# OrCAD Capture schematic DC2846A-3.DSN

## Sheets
1 PAGE2: size A
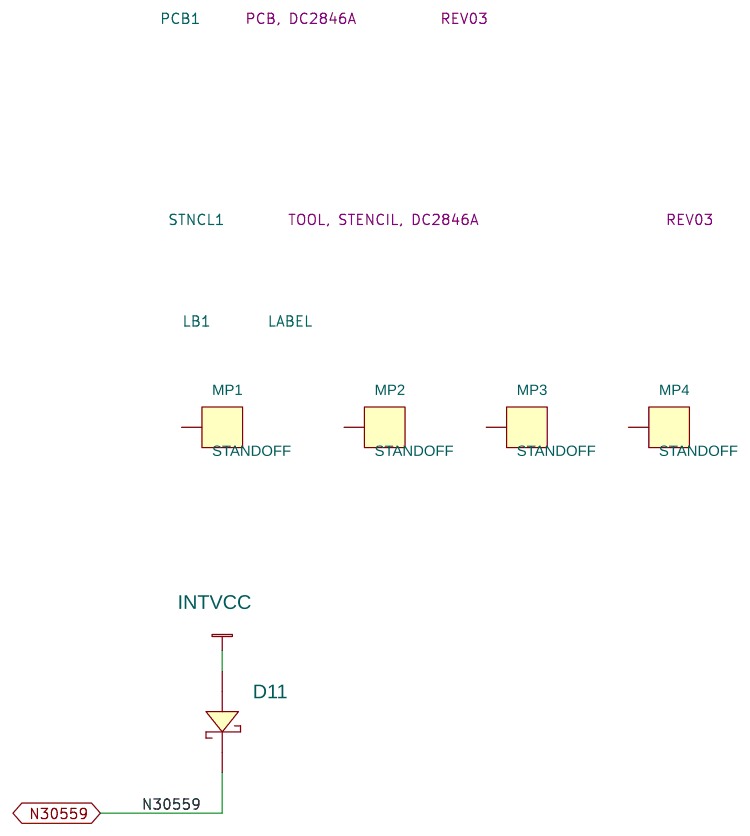
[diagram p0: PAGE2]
2 PAGE1: size Custom; title: HIGH EFFICIENCY, HIGH STEP-DOWN RATIO, SWITCHED CAPACITOR INVERTER; company: LINEAR TECHNOLOGY CORP.; note: DEMO BOARD BILL OF MATERIALS; note: HIGH EFFICIENCY SYNCHRONOUS STEP-UP SUPPLY
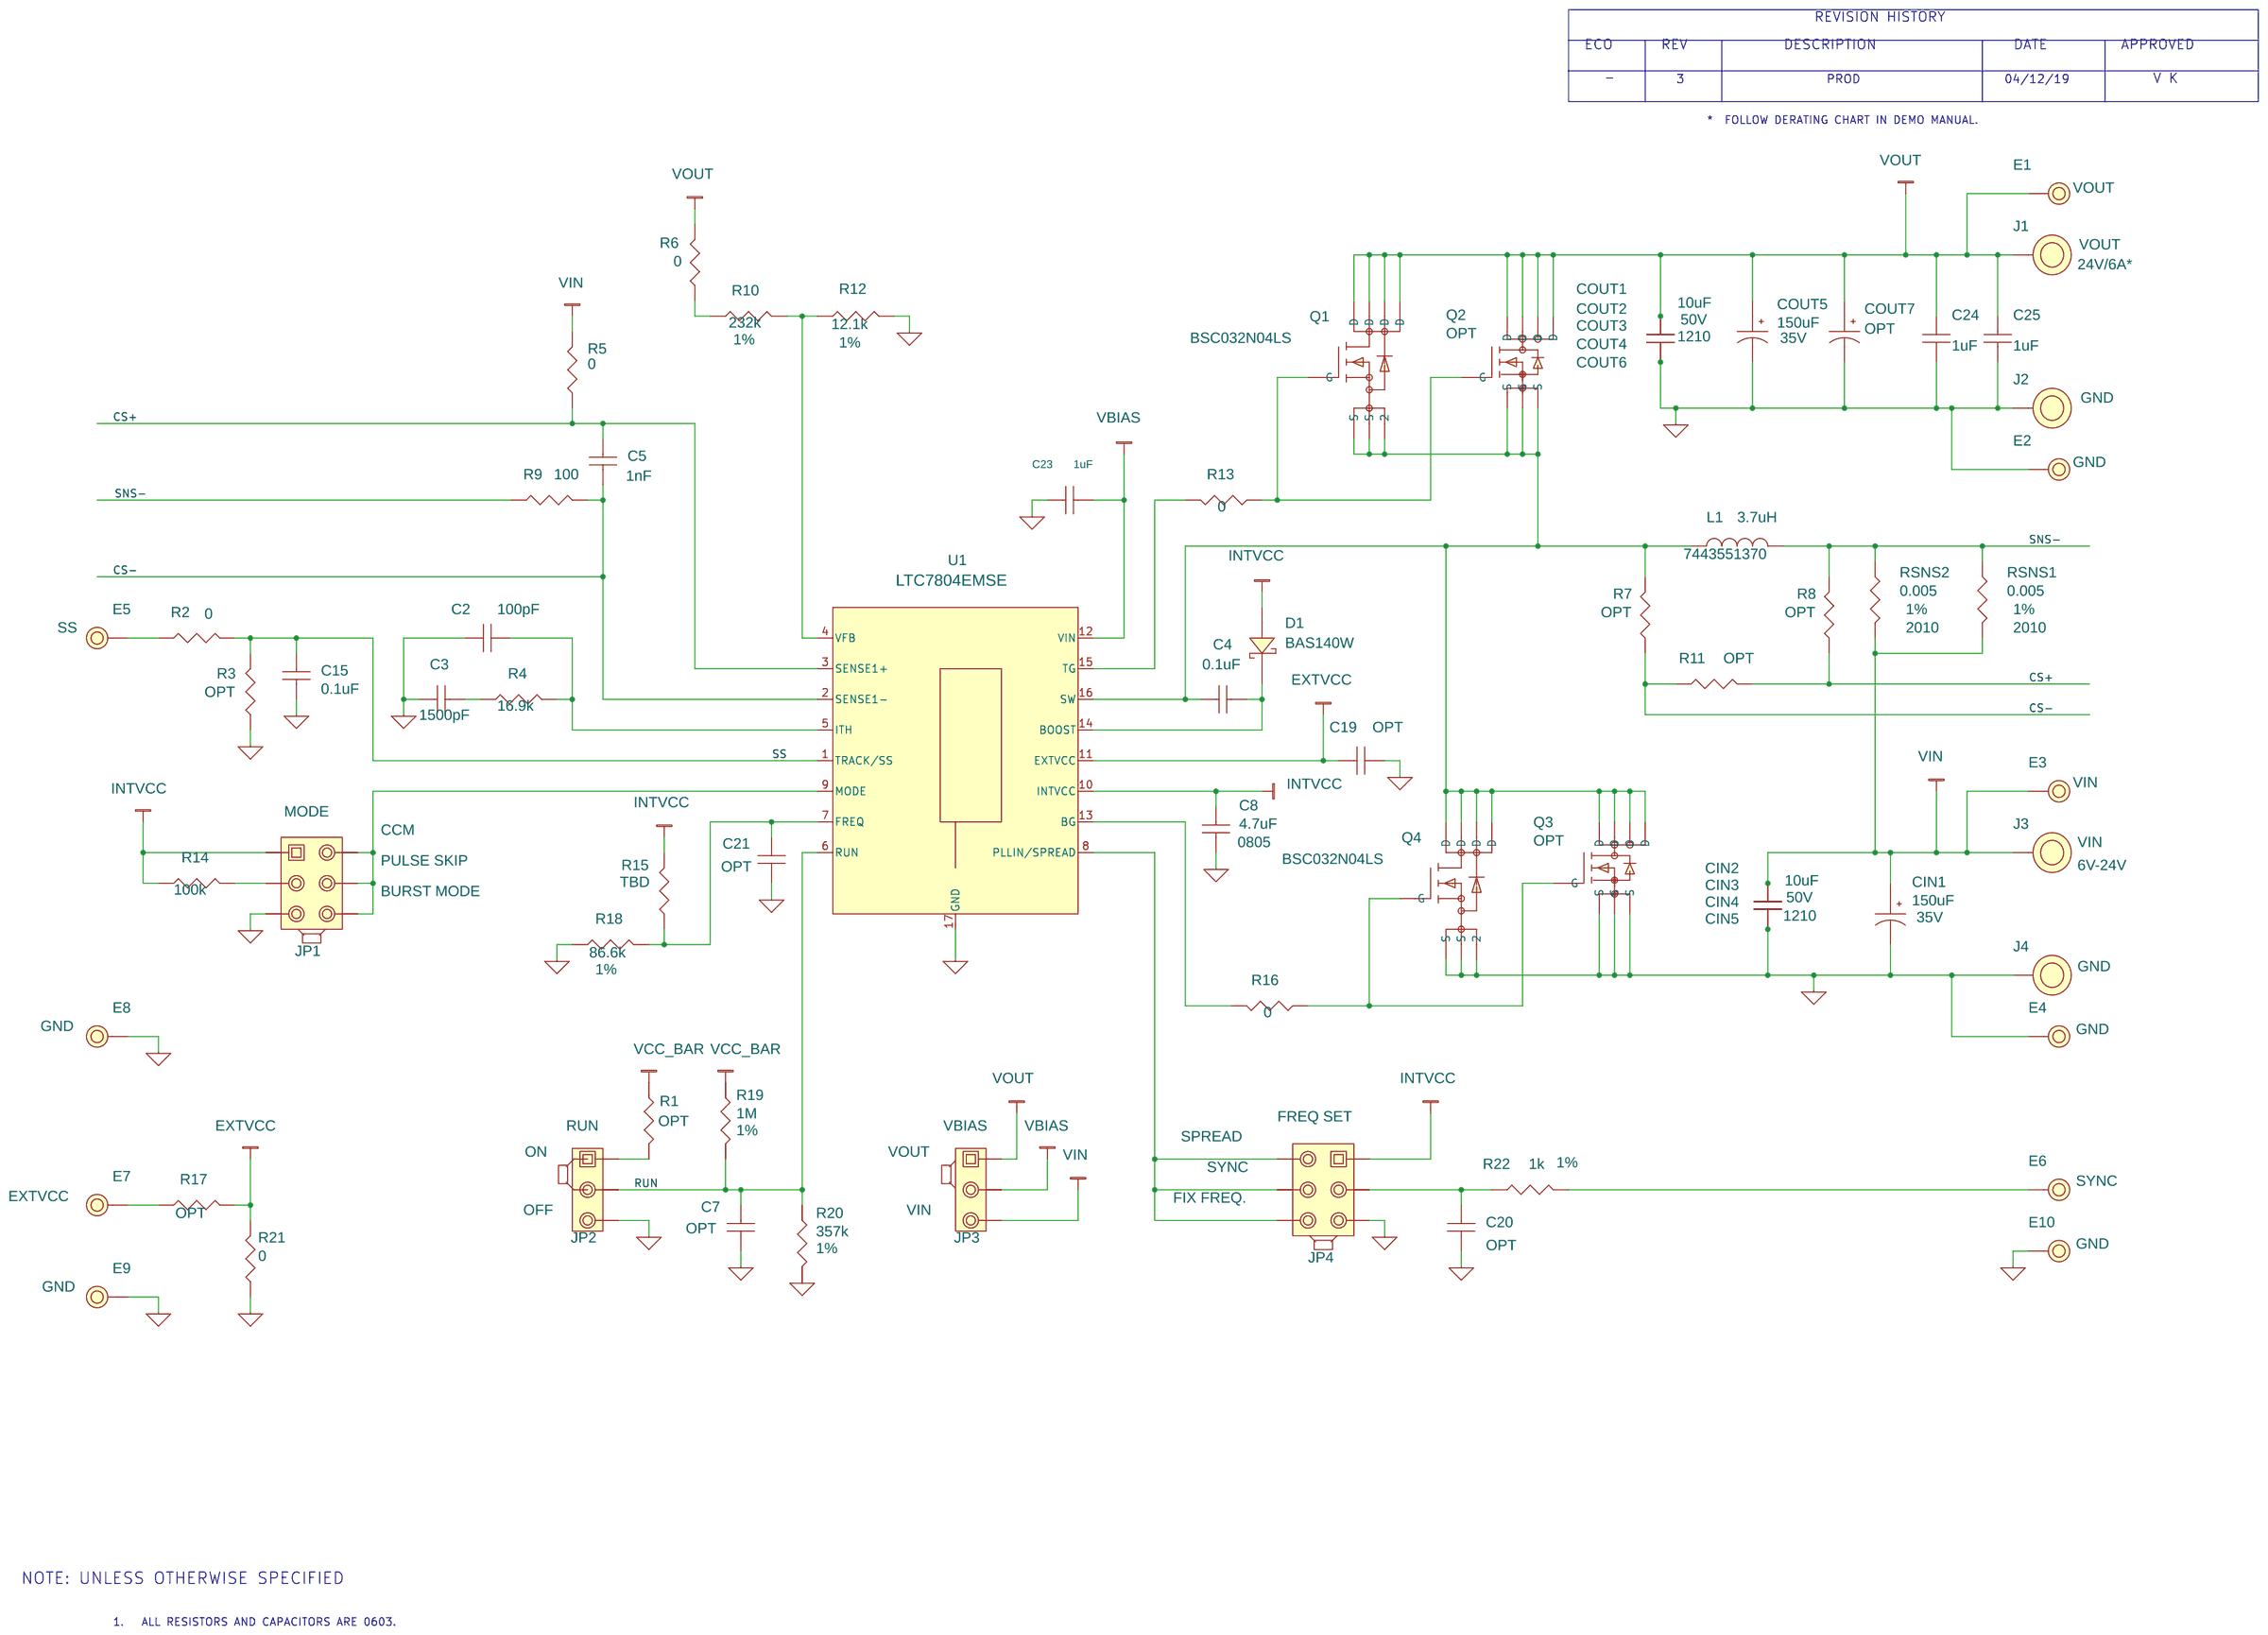
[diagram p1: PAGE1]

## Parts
sheet PAGE1
C2  100pF  [CC0603N]
C3  1500pF  [CC0603N]
C4  0.1uF  [CC0603N]
C5  1000pF  [CC0603N]
C7  OPT  [CC0603N]
C8  4.7uF  [CC0805N]
C15  0.1uF  [CC0603N]
C19  OPT  [CC0603N]
C20  OPT  [CC0603N]
C21  OPT  [CC0603N]
C23  1uF  [CC0603N]
C24  1uF  [CC0805N]
C25  1uF  [CC0805N]
CIN1  150uF  [SUNCON_HVH_10X10.5]
CIN2  10uF  [CC1210N]
CIN3  10uF  [CC1210N]
CIN4  10uF  [CC1210N]
CIN5  10uF  [CC1210N]
COUT1  10uF  [CC1210N]
COUT2  10uF  [CC1210N]
COUT3  10uF  [CC1210N]
COUT4  10uF  [CC1210N]
COUT5  150uF  [CAP\SUNCON\10X10.5]
COUT6  10uF  [CC1210N]
COUT7  OPT  [CAP\SUNCON\10X10.5]
D1  BAS140W  [SOD-323N]
E1  TEST POINT  [MILLMAX2501]
E2  TEST POINT  [MILLMAX2501]
E3  TEST POINT  [MILLMAX2501]
E4  TEST POINT  [MILLMAX2501]
E5  TEST POINT  [MILLMAX2501]
E6  TEST POINT  [MILLMAX2501]
E7  TEST POINT  [MILLMAX2501]
E8  TEST POINT  [MILLMAX2501]
E9  TEST POINT  [MILLMAX2501]
E10  TEST POINT  [MILLMAX2501]
J1  BANANA JACK  [KEY-575-4]
J2  BANANA JACK  [KEY-575-4]
J3  BANANA JACK  [KEY-575-4]
J4  BANANA JACK  [KEY-575-4]
JP1  HDR  [HD2X3-079]
JP2  HDR  [HD1X3-079]
JP3  HDR  [HD1X3-079]
JP4  HDR  [HD2X3-079]
L1  3.7uH  [WURTH-7443551370]
Q1  BSC032N04LS  [INFINEON-PG-TDSON-8]
Q2  OPT  [INFINEON-PG-TDSON-8]
Q3  OPT  [INFINEON-PG-TDSON-8]
Q4  BSC032N04LS  [INFINEON-PG-TDSON-8]
R1  OPT  [CR0603N]
R2  0  [CR0603N]
R3  OPT  [CR0603N]
R4  16.9k  [CR0603N]
R5  0  [CR0603N]
R6  0  [CR0603N]
R7  OPT  [CR0603N]
R8  OPT  [CR0603N]
R9  100  [CR0603N]
R10  232k  [CR0603N]
R11  OPT  [CR0603N]
R12  12.1k  [CR0603N]
R13  0  [CR0603N]
R14  100k  [CR0603N]
R15  TBD  [CR0603N]
R16  0  [CR0603N]
R17  OPT  [CR0603N]
R18  86.6k  [CR0603N]
R19  1M  [CR0603N]
R20  357k  [CR0603N]
R21  0  [CR0603N]
R22  1k  [CR0603N]
RSNS1  0.005  [CR2010N]
RSNS2  0.005  [CR2010N]
U1  LTC7804EMSE  [LTC-MSE-16-1667]
XJP1  SHUNT
XJP4  SHUNT
XJP5  SHUNT
XJP6  SHUNT
sheet PAGE2
D11  BAS140W  [SOD123f]
LB1  LABEL  [895-0154_REV01]
MP1  STANDOFF  [KEYSTONE_8829-8834]
MP2  STANDOFF  [KEYSTONE_8829-8834]
MP3  STANDOFF  [KEYSTONE_8829-8834]
MP4  STANDOFF  [KEYSTONE_8829-8834]
PCB1  PCB, DC2846A
STNCL1  TOOL, STENCIL, 700-DC2846A

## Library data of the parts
C2 = CAP: CAP.,100pF,C0G,25V,10%,0603; CLASS: DISCRETE; Dielectric Type: C0G; FPLIST: CC0603N,CC0603L,CC0603M; Manufacturer: AVX; Manufacturer PN: 06033A101KAT2A; PART_NUMBER: 150-3276; Package Size: 0603; Part Number: AVX 06033A101KAT2A; Rated Voltage: 25V; Tolerance: 10%
C3 = CAP: CAP.,1500pF,X7R,25V,10%,0603; CLASS: DISCRETE; Dielectric Type: X7R; FPLIST: CC0603N,CC0603L,CC0603M; Manufacturer: AVX; Manufacturer PN: 06033C152KAT2A; PART_NUMBER: 150-3370; Package Size: 0603; Part Number: AVX 06033C152KAT2A; Rated Voltage: 25V; Tolerance: 10%
C4 C15 = CAP: CAP.,0.1uF,X5R,25V,10%,0603,NO SUBS. ALLOWED; CLASS: DISCRETE; Dielectric Type: X5R; FPLIST: CC0603N,CC0603L,CC0603M; Manufacturer: AVX; Manufacturer PN: 06033D104KAT2A; PART_NUMBER: 150-3039; Package Size: 0603; Part Number: AVX 06033D104KAT2A; Rated Voltage: 25V; Tolerance: 10%
C5 = CAP: CAP.,1000pF,C0G,25V,10%,0603; BOM Notes: 1nF; CLASS: DISCRETE; Dielectric Type: C0G; FPLIST: CC0603N,CC0603L,CC0603M; Manufacturer: AVX; Manufacturer PN: 06033A102KAT2A; PART_NUMBER: 150-3278; Package Size: 0603; Part Number: AVX 06033A102KAT2A; Rated Voltage: 25V; Tolerance: 10%
C7 = CAP: CAP., OPTION, 0603; CLASS: DISCRETE; FPLIST: CC0603N,CC0603L,CC0603M; PART_NUMBER: 150-3038; Package Size: 0603; Package Type: SMD; Part Number: AVX 06033A102KAT2A
C8 = CAP: CAP.,4.7uF,X5R,25V,10%,0805; CLASS: DISCRETE; Dielectric Type: X5R; FPLIST: CC0805N,CC0805L,CC0805M; Manufacturer: MURATA; Manufacturer PN: GRM219R61E475KA73D; PART_NUMBER: 150-3186; Package Size: 0805; Part Number: MURATA GRM219R61E475KA73D; Rated Voltage: 25V; Tolerance: 10%
C19 = CAP: CAP., OPTION, 0603; CLASS: DISCRETE; FPLIST: CC0603N,CC0603L,CC0603M; PART_NUMBER: 150-3038; Package Size: 0603; Part Number: OPTION; Rated Voltage: 50V; Tolerance: 10%
C20 = CAP: CAP., OPTION, 0603; CLASS: DISCRETE; FPLIST: CC0603N,CC0603L,CC0603M; PART_NUMBER: 150-3038; Package Size: 0603; Package Type: SMD; Part Number: OPTION
C21 = CAP: CAP., OPTION, 0603; CLASS: DISCRETE; FPLIST: CC0603N,CC0603L,CC0603M; PART_NUMBER: 150-3038; Package Size: 0603; Part Number: OPTION
C23 = CAP: CAP.,1uF,X5R,50V,10%,0603; CLASS: DISCRETE; Dielectric Type: X5R; FPLIST: CC0603N,CC0603L,CC0603M; Manufacturer: AVX; Manufacturer PN: 06035D105KAT2A; PART_NUMBER: 150-2570; Package Size: 0603; Part Number: TDK CGA3E1X7R1E105K080AC; Rated Voltage: 50V; Tolerance: 10%
C24 C25 = CAP: CAP.,1uF,X7R,50V,10%,0805; CLASS: DISCRETE; Dielectric Type: X7R; Inventory Qty: 4400; Manufacturer: AVX; Manufacturer PN: 08055C105KAT2A; PART_NUMBER: 150-2373; Package Size: 0805; Rated Voltage: 50V; Tolerance: 10%
CIN1 = CAP_P: CAP.,150uF,ALUM. ELECT.,35V,20%,10mmX10.5mm RADIAL, SMD,HVH Series; CLASS: DISCRETE; Dielectric Type: ALUM. ELECT.; Manufacturer: SUN ELECTRONIC INDUSTRIES CORP; Manufacturer PN: 35HVH150M; PART_NUMBER: 150-3275; Package Size: 10mmX10.5mm RADIAL, SMD; Part Number: SUNCON 35HVH150M; Rated Voltage: 35V; Tolerance: 20%
CIN2-CIN5 COUT1-COUT4 COUT6 = CAP: CAP.,10uF,X5R,50V,10%,1210; CLASS: DISCRETE; Dielectric Type: X5R; FPLIST: CC1210N,CC1210L,CC1210M; Manufacturer: TDK; Manufacturer PN: C3225X5R1H106K250AB; PART_NUMBER: 150-3288; Package Size: 1210; Part Number: TDK C3225X5R1H106K250AB; Rated Voltage: 50V; Tolerance: 10%
COUT5 = CAP_P: CAP.,150uF,ALUM. ELECT.,35V,20%,SMD; CLASS: DISCRETE; Dielectric Type: ALUM. ELECT.; Manufacturer: SUNCON; Manufacturer PN: 35HVH150M; PART_NUMBER: 150-3275; Package Size: SMD; Part Number: SUNCON 35HVH150M; Rated Voltage: 35V; Tolerance: 20%
COUT7 = CAP_P_ALT: CAP.,OPTION,ALUM. ELECT.,SMD; CLASS: DISCRETE; PART_NUMBER: 150-0497; Package Type: SMD
D1 = DIODE_SCHOTTKY_A_ALT: DIODE,SCHOTTKY,40V,120mA,SOD323-2,AEC-Q101; CLASS: DISCRETE; FPLIST: SOD-323N,SOD-323L,SOD-323M; Inventory Qty: 5216; Manufacturer: INFINEON; Max Forward Current or Rated Power: 250mW; PART_NUMBER: 210-0094; Package Type: SOD323-2; Rated Voltage or Zener Voltage: 40V
E1 = TESTPOINT_.219_MILL-MAX_2501: TEST POINT,TURRET,0.094",MTG. HOLE; 1st Part Field: VOUT; CLASS: IO; FPLIST: MILLMAX2501,MILLMAX2501_ALT1; Manufacturer: MILL-MAX; Manufacturer PN: 2501-2-00-80-00-00-07-0; PART_NUMBER: 260-0003; Part Number: MILL-MAX 2501-2-00-80-00-00-07-0
E2 E4 E8-E10 = TESTPOINT_.219_MILL-MAX_2501: TEST POINT,TURRET,0.094",MTG. HOLE; 1st Part Field: GND; CLASS: IO; FPLIST: MILLMAX2501,MILLMAX2501_ALT1; Manufacturer: MILL-MAX; Manufacturer PN: 2501-2-00-80-00-00-07-0; PART_NUMBER: 260-0003; Part Number: MILL-MAX 2501-2-00-80-00-00-07-0
E3 = TESTPOINT_.219_MILL-MAX_2501: TEST POINT,TURRET,0.094",MTG. HOLE; 1st Part Field: VIN; CLASS: IO; FPLIST: MILLMAX2501,MILLMAX2501_ALT1; Manufacturer: MILL-MAX; Manufacturer PN: 2501-2-00-80-00-00-07-0; PART_NUMBER: 260-0003; Part Number: MILL-MAX 2501-2-00-80-00-00-07-0
E5 = TESTPOINT_.219_MILL-MAX_2501: TEST POINT,TURRET,0.094",MTG. HOLE; 1st Part Field: SS; CLASS: IO; FPLIST: MILLMAX2501,MILLMAX2501_ALT1; Manufacturer: MILL-MAX; Manufacturer PN: 2501-2-00-80-00-00-07-0; PART_NUMBER: 260-0003; Part Number: MILL-MAX 2501-2-00-80-00-00-07-0
E6 = TESTPOINT_.219_MILL-MAX_2501: TEST POINT,TURRET,0.094",MTG. HOLE; 1st Part Field: SYNC; CLASS: IO; FPLIST: MILLMAX2501,MILLMAX2501_ALT1; Manufacturer: MILL-MAX; Manufacturer PN: 2501-2-00-80-00-00-07-0; PART_NUMBER: 260-0003; Part Number: MILL-MAX 2501-2-00-80-00-00-07-0
E7 = TESTPOINT_.219_MILL-MAX_2501: TEST POINT,TURRET,0.094",MTG. HOLE; 1st Part Field: EXTVCC; 2nd Part Field: 28V MAX; CLASS: IO; FPLIST: MILLMAX2501,MILLMAX2501_ALT1; Manufacturer: MILL-MAX; Manufacturer PN: 2501-2-00-80-00-00-07-0; PART_NUMBER: 260-0003; Part Number: MILL-MAX 2501-2-00-80-00-00-07-0
J1 = BANANA_KEYSTONE-575-4: CONN.,BANANA JACK,FEMALE,THT,NON-INSULATED, SWAGE; 1st Part Field: VOUT; 2nd Part Field: 24V/6A*; CLASS: IO; Manufacturer: KEYSTONE; Manufacturer PN: 575-4; PART_NUMBER: 250-0428; Part Number: KEYSTONE 575-4
J2 J4 = BANANA_KEYSTONE-575-4: CONN.,BANANA JACK,FEMALE,THT,NON-INSULATED, SWAGE; 1st Part Field: GND; CLASS: IO; Manufacturer: KEYSTONE; Manufacturer PN: 575-4; PART_NUMBER: 250-0428; Part Number: KEYSTONE 575-4
J3 = BANANA_KEYSTONE-575-4: CONN.,BANANA JACK,FEMALE,THT,NON-INSULATED, SWAGE; 1st Part Field: VIN; 2nd Part Field: 6V-24V; CLASS: IO; Manufacturer: KEYSTONE; Manufacturer PN: 575-4; PART_NUMBER: 250-0428; Part Number: KEYSTONE 575-4
JP1 = HDR2X3_ALT1: CONN.,HDR,MALE,2x3,2mm,VERT, STR, THT; 1st Part Field: CCM; 2nd Part Field: PULSE SKIP; 3rd Part Fiels: BURST MODE; 9th Part Field: MODE; CLASS: IO; Manufacturer: WURTH ELEKTRONIK; Manufacturer PN: 62000621121; PART_NUMBER: 250-0483; Part Number: WURTH ELEKTRONIK 62000621121
JP2 = 1X3_A: CONN.,HDR,MALE,1x3,2mm,STR, THT,NO SUBS. ALLOWED; 11th Part Field: OFF; 12th Part Field: RUN; 9th Part Field: ON; CLASS: IO; Manufacturer: Wurth Elektronik; Manufacturer PN: 62000311121; PART_NUMBER: 250-0639; Part Number: WURTH ELEKTRONIK 62000621121
JP3 = 1X3_A: CONN.,HDR,MALE,1x3,2mm,STR, THT,NO SUBS. ALLOWED; 11th Part Field: VIN; 12th Part Field: VBIAS; 9th Part Field: VOUT; CLASS: IO; Manufacturer: Wurth Elektronik; Manufacturer PN: 62000311121; PART_NUMBER: 250-0639; Part Number: WURTH ELEKTRONIK 62000621121
JP4 = HDR2X3_ALT1: CONN.,HDR,MALE,2x3,2mm,VERT, STR, THT; 1st Part Field: SPREAD; 2nd Part Field: SYNC; 3rd Part Fiels: FIX FREQ.; 9th Part Field: FREQ SET; CLASS: IO; Manufacturer: WURTH ELEKTRONIK; Manufacturer PN: 62000621121; PART_NUMBER: 250-0483; Part Number: WURTH ELEKTRONIK 62000621121
L1 = IND_ALT: IND.,3.7uH WE-HCI FLAT WIRE HIGH CURRENT SMD; CLASS: DISCRETE; Manufacturer: WURTH ELEKTRONIK; Manufacturer PN: 7443551370; PART_NUMBER: 200-0652; Package Size: 6.2mmX12.8mmX12.8mm; Tolerance: 20%
Q1 Q4 = 8P_N-CH_TYPE1A: XSTR.,MOSFET, N-CH,40V,98A,TDSON-8; CLASS: DISCRETE; Manufacturer: INFINEON; PART_NUMBER: 240-0252; Package Size: TDSON-8; Package Type: TDSON-8; Part Number: INFINEON BSC032N04LS; Polarity: N-Channel; Rated Voltage: 40V
Q2 Q3 = 8P_N-CH_TYPE1C: XSTR., OPTION, MOSFET N-CH, PG-TDSON-8; CLASS: DISCRETE; PART_NUMBER: 240-0350; Package Type: PG-TDSON-8; Part Number: OPTION
R1 R3 R7 R8 R11 R15 R17 = RES: RES., OPTION, 0603; CLASS: DISCRETE; FPLIST: CR0603N,CR0603L,CR0603M; PART_NUMBER: 100-2374; Package Size: 0603; Part Number: OPTION
R2 R5 R6 R13 R16 = RES: RES.,AEC-Q200,0 OHM,1/10W,0603; CLASS: DISCRETE; FPLIST: CR0603N,CR0603L,CR0603M; Manufacturer: VISHAY; Manufacturer PN: CRCW06030000Z0EA; PART_NUMBER: 100-0009; Package Size: 0603; Part Number: VISHAY CRCW06030000Z0EA; Rated Power: 1/10W
R4 = RES: RES.,AEC-Q200,16.9k OHMS,1%,1/10W,0603; CLASS: DISCRETE; FPLIST: CR0603N,CR0603L,CR0603M; Manufacturer: VISHAY; Manufacturer PN: CRCW060316K9FKEA; PART_NUMBER: 100-2653; Package Size: 0603; Part Number: VISHAY CRCW060316K9FKEA; Rated Power: 1/10W; Temperature Coefficient: 100ppm; Tolerance: 1%
R9 = RES: RES.,100 OHMS,1%,1/10W,0603; CLASS: DISCRETE; FPLIST: CR0603N,CR0603L,CR0603M; Manufacturer: YAGEO; Manufacturer PN: RC0603FR-07100RL; PART_NUMBER: 100-0150; Package Size: 0603; Part Number: VISHAY CRCW0603100RFKEA; Rated Power: 1/10W; Temperature Coefficient: 100ppm/C; Tolerance: 1%
R10 = RES: RES.,AEC-Q200,232k OHMS,1%,1/10W,0603; CLASS: DISCRETE; FPLIST: CR0603N,CR0603L,CR0603M; Manufacturer: VISHAY; Manufacturer PN: CRCW0603232KFKEA; PART_NUMBER: 100-2654; Package Size: 0603; Part Number: VISHAY CRCW0603232KFKEA; Rated Power: 1/10W; Temperature Coefficient: 100ppm/C; Tolerance: 1%
R12 = RES: RES.,AEC-Q200,12.1k OHMS,1%,1/10W,0603; CLASS: DISCRETE; FPLIST: CR0603N,CR0603L,CR0603M; Manufacturer: VISHAY; Manufacturer PN: CRCW060312K1FKEA; PART_NUMBER: 100-2655; Package Size: 0603; Part Number: VISHAY CRCW060314K7FKEA; Rated Power: 1/10W; Temperature Coefficient: 100ppm/C; Tolerance: 1%
R14 = RES: RES.,AEC-Q200,100k OHMS,1%,1/10W,0603; CLASS: DISCRETE; FPLIST: CR0603N,CR0603L,CR0603M; Manufacturer: VISHAY; Manufacturer PN: CRCW0603100KFKEA; PART_NUMBER: 100-0343; Package Size: 0603; Part Number: VISHAY CRCW0603100KFKEA; Rated Power: 1/10W; Temperature Coefficient: +/-100ppm; Tolerance: 1%
R18 = RES: RES.,86.6k OHMS,1%,1/10W,0603,AEC-Q200; CLASS: DISCRETE; FPLIST: CR0603N,CR0603L,CR0603M; Inventory Qty: 99700; Manufacturer: PANASONIC; Manufacturer PN: ERJ3EKF8662V; PART_NUMBER: 100-2711; Package Size: 0603; Part Number: VISHAY CRCW060376K2FKEA; Rated Power: 1/10W; Temperature Coefficient: +/-100ppm; Tolerance: 1%
R19 = RES: RES.,AEC-Q200,1M OHM,1%,1/10W,0603; CLASS: DISCRETE; FPLIST: CR0603N,CR0603L,CR0603M; Manufacturer: VISHAY; Manufacturer PN: CRCW06031M00FKEA; PART_NUMBER: 100-0335; Package Size: 0603; Part Number: VISHAY CRCW06031M00FKEA; Rated Power: 1/10W; Temperature Coefficient: 100ppm; Tolerance: 1%
R20 = RES: RES.,357k OHMS,1%,1/10W,0603,AEC-Q200; CLASS: DISCRETE; FPLIST: CR0603N,CR0603L,CR0603M; Inventory Qty: 30000; Manufacturer: PANASONIC; Manufacturer PN: ERJ3EKF3573V; PART_NUMBER: 100-0089; Package Size: 0603; Part Number: VISHAY CRCW060348K7FKEA; Rated Power: 1/10W; Temperature Coefficient: 100ppm/C; Tolerance: 1%
R21 = RES: RES.,0 OHM,1/10W,0603,AEC-Q200; CLASS: DISCRETE; FPLIST: CR0603N,CR0603L,CR0603M; Inventory Qty: 645747; Manufacturer: VISHAY; Manufacturer PN: CRCW06030000Z0EA; PART_NUMBER: 100-0009; Package Size: 0603; Rated Power: 1/10W
R22 = RES: RES.,AEC-Q200,1k OHM,1%,1/10W,0603; CLASS: DISCRETE; Manufacturer: VISHAY; Manufacturer PN: CRCW06031K00FKEA; PART_NUMBER: 100-2422; Package Size: 0603; Part Number: VISHAY CRCW06031K00FKEA; Rated Power: 1/10W; Temperature Coefficient: 100ppm; Tolerance: 1%
RSNS1 RSNS2 = RES: RES.,SENSE, AEC-Q200,0.005 OHM,1%,1/2W,2010; CLASS: DISCRETE; FPLIST: CR2010N,CR2010L,CR2010M; Manufacturer: VISHAY; Manufacturer PN: WSL20105L000FEA; PART_NUMBER: 100-2652; Package Size: 2010; Part Number: VISHAY WSL20105L000FEA; Rated Power: 1/2W; Temperature Coefficient: 110ppm/C; Tolerance: 1%
U1 = LTC7804-MSE: IC,Low IQ Sync. Boost Controller,SSOP-16; CLASS: IC; Manufacturer: ANALOG DEVICES INC.; Manufacturer PN: LTC7804EMSE#PBF; PART_NUMBER: LTC7804EMSE#PBF; Package Type: SSOP-16
XJP1 XJP4-XJP6 = SHUNT_2MM: CONN.,SHUNT,FEMALE,2 POS,2mm; CLASS: IO; Manufacturer: Wurth Elektronik; Manufacturer PN: 60800213421; PART_NUMBER: 250-0485; Part Number: WURTH ELEKTRONIK 60800213421
D11 = DIODE_SCHOTTKY_A_ALT: DIODE,SCHOTTKY,40V,120mA,SOD323-2,AEC-Q101; BOM Notes: NO STUFF; CLASS: DISCRETE; FPLIST: SOD-323N,SOD-323L,SOD-323M; Inventory Qty: 5216; Max Forward Current or Rated Power: 250mW; PART_NUMBER: 210-0115; Package Type: SOD323-2; Rated Voltage or Zener Voltage: 40V
LB1 = BLANK_LABEL: LABEL SPEC, DEMO BOARD SERIAL NUMBER; Manufacturer: BRADY; Manufacturer PN: THT-96-717-10; PART_NUMBER: 895-0154
MP1-MP4 = MP-PINNED: STANDOFF,NYLON,SNAP-ON,0.625"; CLASS: DISCRETE; Inventory Qty: 149403; Manufacturer: KEYSTONE; Manufacturer PN: 8834; PART_NUMBER: 763-0013
PCB1 = BLANK_PCB_PART: BOM Notes: REV03; CLASS: DISCRETE; Manufacturer: PHASE 3 TECHNOLOGIES INC.; Manufacturer PN: 600-DC2846A; PART_NUMBER: 600-DC2846A
STNCL1 = BLANK_STENCIL_PART: TOOL, STENCIL, DC2846A; BOM Notes: REV03; CLASS: DISCRETE; Manufacturer: LINEAR TECH.; Manufacturer PN: 830-DC2846A; PART_NUMBER: 830-DC2846A

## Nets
GND: C2.1 C3.1 C7.2 C8.2 C15.2 C19.2 C20.2 C21.2 C23.1 C24.2 C25.2 CIN1.2 CIN2.2 CIN3.2 CIN4.2 CIN5.2 COUT1.2 COUT2.2 COUT3.2 COUT4.2 COUT5.2 COUT6.2 COUT7.2 E2.1 E4.1 E8.1 E9.1 E10.1 J2.1 J4.1 JP1.5 JP2.3 JP4.5 Q3.1(S) Q3.2(S) Q3.3(S) Q4.1(S) Q4.2(S) Q4.3(2) R3.2 R12.1 R18.1 R20.2 R21.2 U1.17(GND)
VIN: CIN1.1 CIN2.1 CIN3.1 CIN4.1 CIN5.1 E3.1 J3.1 JP3.3 R1.1 R5.2 R19.1 RSNS1.2 RSNS2.2
CS+: C5.1 R5.1 R8.2 R11.2 U1.3(SENSE1+)
CS-: C5.2 R7.2 R9.2 R11.1 U1.2(SENSE1-)
EXTVCC: C19.1 R17.2 R21.1 U1.11(EXTVCC)
INTVCC: C8.1 D1.2(A) D11.2(A) JP1.1 JP4.1 R14.1 R15.1 U1.10(INTVCC)
N30559 (page PAGE2): D11.1(C)
RUN: C7.1 JP2.2 R19.2 R20.1 U1.6(RUN)
SNS-: L1.1 R8.1 R9.1 RSNS1.1 RSNS2.1
SS: C15.1 R2.2 R3.1 U1.1(TRACK/SS)
VBIAS: C23.2 JP3.2 U1.12(VIN)
VOUT: C24.1 C25.1 COUT1.1 COUT2.1 COUT3.1 COUT4.1 COUT5.1 COUT6.1 COUT7.1 E1.1 J1.1 JP3.1 Q1.5(D) Q1.6(D) Q1.7(D) Q1.8(D) Q2.5(D) Q2.6(D) Q2.7(D) Q2.8(D) R6.1
N29667: Q1.4(G) Q2.4(G) R13.2
N29739: C4.1 L1.2 Q1.1(S) Q1.2(S) Q1.3(2) Q2.1(S) Q2.2(S) Q2.3(S) Q3.5(D) Q3.6(D) Q3.7(D) Q3.8(D) Q4.5(D) Q4.6(D) Q4.7(D) Q4.8(D) R7.1 U1.16(SW)
N29829: R13.1 U1.15(TG)
N29867: C2.2 R4.2 U1.5(ITH)
N29963: R6.2 R10.1
N30011: R10.2 R12.2 U1.4(VFB)
N30143: E5.1 R2.1
N30559: C4.2 D1.1(C) U1.14(BOOST)
N30763: JP1.2 JP1.4 JP1.6 U1.9(MODE)
N30799: C21.1 R15.2 R18.2 U1.7(FREQ)
N30807: R16.1 U1.13(BG)
N31129: Q3.4(G) Q4.4(G) R16.2
N96508: JP1.3 R14.2
N102359: JP2.1 R1.2
N106735: E7.1 R17.1
N108776: JP4.2 JP4.4 JP4.6 U1.8(PLLIN/SPREAD)
N109735: C20.1 JP4.3 R22.1
N109744: E6.1 R22.2
N110783: C3.2 R4.1

Not connected (* = marked no-connect by the designer): MP1 1; MP2 1; MP3 1; MP4 1

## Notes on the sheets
sheet 2
- REVISION HISTORY
- ECO
- REV
- DESCRIPTION
- DATE
- APPROVED
- -
- 3
- PROD
- 04/12/19
- V K
- *  FOLLOW DERATING CHART IN DEMO MANUAL.
- NOTE: UNLESS OTHERWISE SPECIFIED
- 1.   ALL RESISTORS AND CAPACITORS ARE 0603.
